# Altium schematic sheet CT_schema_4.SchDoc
size 226 x 258 mm
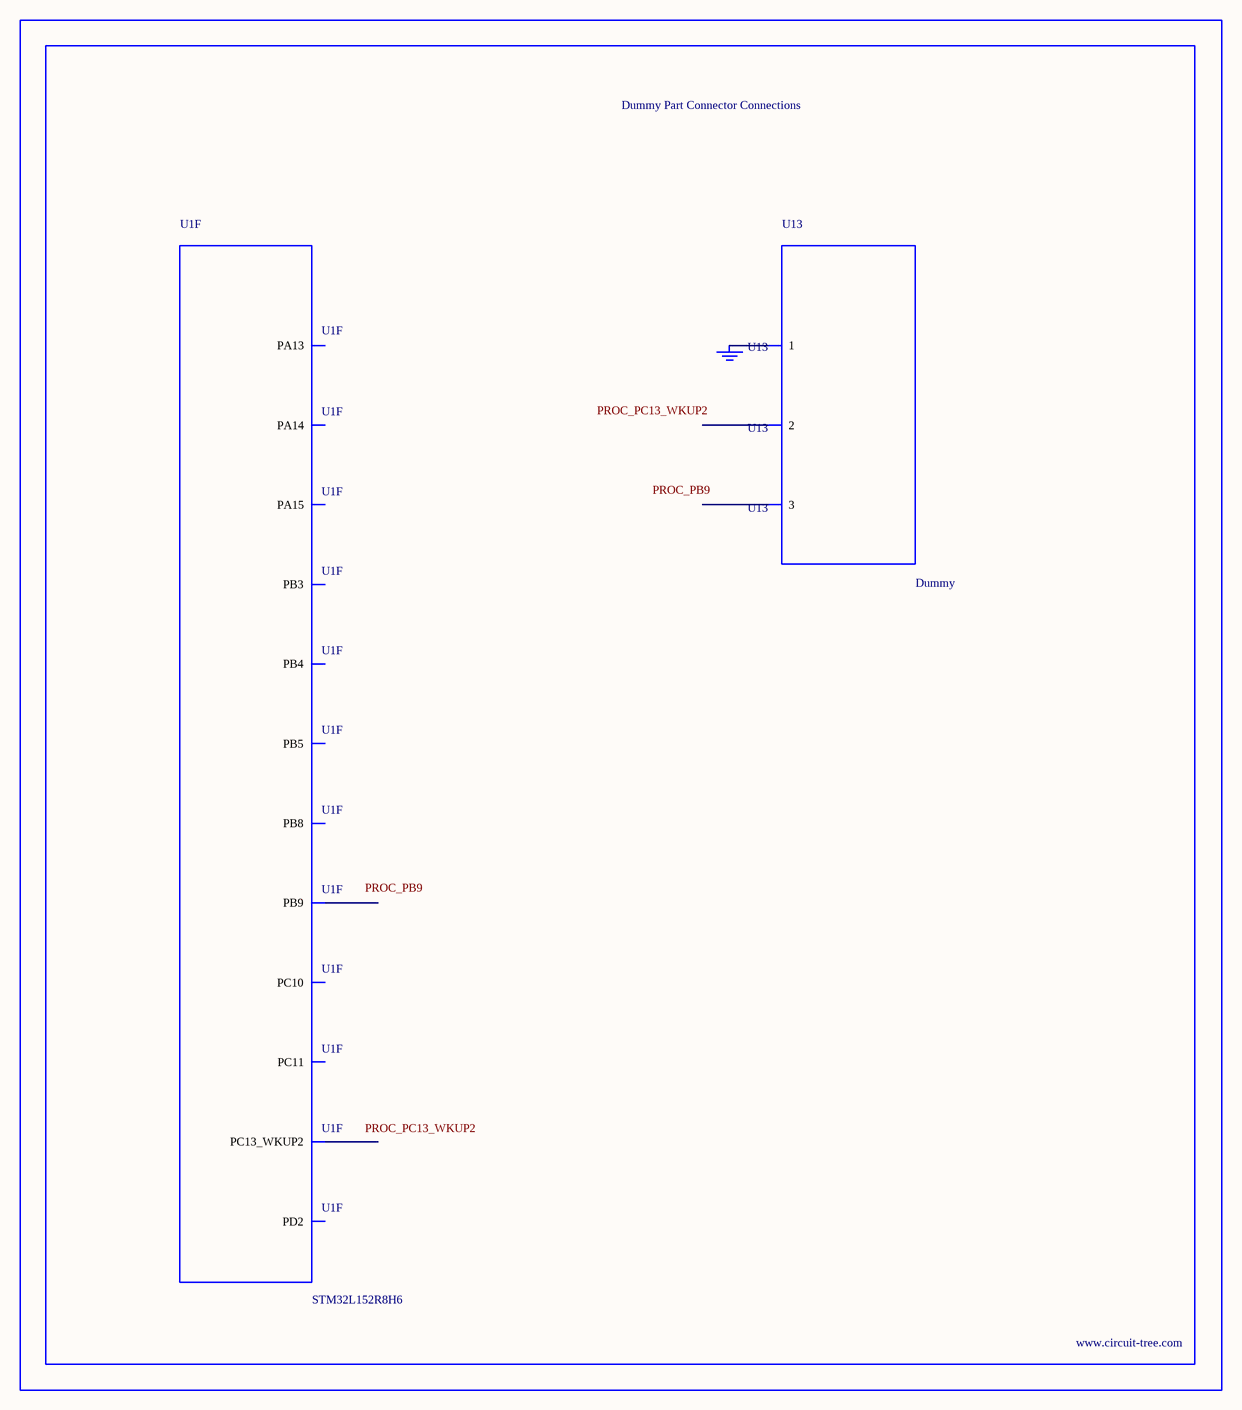
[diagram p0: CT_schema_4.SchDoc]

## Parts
BORDER3  (no value)
GND_INSTANCE_3_0  (no value)
U1  STM32L152R8H6  [TFBGA64]  (part F of 6)
U13  Dummy  [DUMMY_PACKAGE_119]

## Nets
NetGND_INSTANCE_3_0_0: GND_INSTANCE_3_0.0(GND) U13.1

Not connected (* = marked no-connect by the designer): U1 A2(PC13_WKUP2) A3(PB9) A4(PB4) A5(PB3) A6(PA15) A7(PA14) A8(PA13) B3(PB8) B5(PD2) B6(PC11) B7(PC10) C4(PB5); U13 2 3

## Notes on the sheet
- Labels drawn without touching a wire or pin: PROC_PB9, PROC_PC13_WKUP2

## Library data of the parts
BORDER3 = BORDER_PAGE3
GND_INSTANCE_3_0 = GND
